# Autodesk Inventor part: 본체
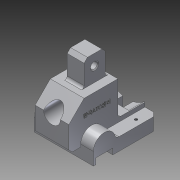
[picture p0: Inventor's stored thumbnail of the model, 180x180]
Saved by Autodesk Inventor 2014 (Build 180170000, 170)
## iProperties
Created: 2016-11
Part Number: 본체
Material: Aluminum 6061
Document SubType Name: Modeling
Designer: user
Density: 2.71 g/cm^3
Appearance: Aluminum - Flat
Author: user
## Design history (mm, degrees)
sketch "Sketch1"
  geometry: L1 (0, 0)-(0, 15); L2 (26, 15)-(76, 15); L3 (76, 15)-(76, 0); L4 (76, 0)-(0, 0); A1 r 13 centre (13, 15) between (26, 15) and (0, 15)
  constraints: 8 end point, 2 parallel, 2 point on circle, 1 centre point, 1 horizontal alignment, 1 perpendicular, 1 point on line, 1 vertical
  dimensions: "d1" = 15 distance of L1.start L1.end; "d2" = 76 distance of L3.end L1.start; "d3" = 26 diameter of A1
extrude "Extrusion1" new body sketch "Sketch1" distance "d4" = 70; taper "d5" = 0 deg
sketch "Sketch2"
  geometry: L1 (0, 0)-(-15, 0) reference; L2 (0, 76)-(0, 0) reference; L3 (-15, 26)-(-15, 76) reference; L4 (0, 3)-(-7, 3); L5 (-7, 3)-(-7, 23); L6 (-7, 23)-(0, 23)
  constraints: 6 end point, 3 perpendicular, 2 point on line
  dimensions: "d6" = 7 distance of L5.end L6.end; "d7" = 20 distance of L4.end L5.end; "d8" = 3 distance between parallel lines of L1 L4
extrude "Extrusion2" cut sketch "Sketch2" distance "d9" = 70; taper "d10" = 0 deg
workplane "Work Plane1"
sketch "Sketch3"
  geometry: L1 (23, 0)-(23, 7) reference; L2 (23, 7)-(3, 7) reference; L3 (3, 7)-(3, 0) reference; L4 (3, 0)-(0, 0) reference; L5 (0, 0)-(0, 15) reference; L6 (26, 15)-(76, 15) reference; L7 (76, 15)-(76, 0) reference; L8 (76, 0)-(23, 0) reference; L9 (76, 15)-(76, 20); L10 (76, 20)-(44, 20); L11 (44, 20)-(44, 15); A1 r 13 centre (13, 15) between (26, 15) and (0, 15) reference; 1 further point
  constraints: 6 end point, 3 perpendicular, 1 point on line
  dimensions: "d12" = 32 distance of L9.end L10.end; "d13" = 5 distance of L10.end L11.end
extrude "Extrusion3" join sketch "Sketch3" distance "d14" = 40; taper "d15" = 0 deg
sketch "Sketch4"
  geometry: L1 (23, 0)-(23, 7) reference; L2 (23, 7)-(3, 7) reference; L3 (3, 7)-(3, 0) reference; L4 (3, 0)-(0, 0) reference; L5 (0, 0)-(0, 15) reference; L6 (26, 15)-(76, 15) reference; L7 (76, 15)-(76, 0) reference; L8 (76, 0)-(23, 0) reference; L9 (76, 20)-(76, 15) reference; L10 (44, 15)-(76, 15) reference; L11 (44, 15)-(44, 20) reference; L12 (44, 20)-(76, 20) reference; L13 (44, 20)-(44, 60); L14 (44, 60)-(4, 60); L15 (4, 60)-(-14, 42); L16 (-14, 42)-(-14, 12); L17 (-14, 12)-(0, 12); L18 (44, 20)-(44, 15); L19 (44, 15)-(26, 15); L20 (0, 15)-(0, 12); A1 r 13 centre (13, 15) between (26, 15) and (0, 15) reference; A2 r 13 centre (13, 15) between (26, 15) and (0, 15); 1 further point
  constraints: 16 end point, 5 perpendicular, 2 parallel, 2 point on circle, 2 point on line, 2 tangent, 1 centre point, 1 coincident, 1 collinear
  dimensions: "d18" = 45 deg angle of L15 L14; "d21" = 48 distance between parallel lines of L17 L14; "d22" = 60 distance between parallel lines of L8 L14; "d23" = 30 distance of L15.end L16.end; "d24" = 40 distance of L13.end L14.end
extrude "Extrusion4" join sketch "Sketch4" distance "d25" = 40; taper "d26" = 0 deg
workplane "Work Plane2"
sketch "Sketch5"
  geometry: L1 (44, 60)-(4, 60) reference; L2 (39, 60)-(39, 90); L3 (39, 90)-(14, 90); L4 (14, 90)-(14, 60); L5 (39, 60)-(14, 60); L6 (76, 0)-(23, 0) reference; L7 (44, 60)-(44, 20) reference; 1 further point
  constraints: 8 end point, 3 perpendicular, 2 point on line, 1 collinear
  dimensions: "d28" = 90 distance between parallel lines of L6 L3; "d29" = 25 distance of L2.end L3.end; "d30" = 5 distance between parallel lines of L7 L2
extrude "Extrusion5" join sketch "Sketch5" stored distance "d31" = 20; taper "d32" = 0 deg
sketch "Sketch6"
  geometry: L1 (0, 15)-(-70, 15) reference; C1 r 29 at (-35, -27); 1 further point
  constraints: 1 centre point, 1 midpoint, 1 vertical alignment
  dimensions: "d33" = 58 diameter of C1; "d34" = 42 distance from line of L1 C1.centre
extrude "Extrusion6" cut sketch "Sketch6" distance "d35" = 18; taper "d36" = 0 deg
sketch "Sketch7"
  geometry: L1 (0, 15)-(-70, 15) reference; L2 (-53.894, -5)-(-55, -5) reference; L3 (-29, 15)-(-29, 1.373); L4 (-41, 15)-(-41, 1.373); L5 (-41, 15)-(-29, 15); A1 r 29 centre (-35, -27) between (-16.106, -5) and (-53.894, -5) reference; 2 further points
  constraints: 6 end point, 2 midpoint, 2 point on circle, 2 point on line, 2 vertical alignment, 1 parallel, 1 perpendicular
  dimensions: "d37" = 12 distance between parallel lines of L4 L3
extrude "Extrusion7" cut sketch "Sketch7" distance "d38" = 18; taper "d39" = 0 deg
sketch "Sketch8"
  geometry: L1 (0, 0)-(0, 50) reference; L2 (0, 50)-(-15, 50) reference; L3 (-55, 50)-(-70, 50) reference; 3 further points
  dimensions: "d40" = 18 distance from line of L2 point (-7.5, 32); "d41" = 18 distance from line of L3 point (-62.5, 32); "d42" = 55 distance of point (-7.5, 32) point (-62.5, 32); "d43" = 7.5 distance from line of L1 point (-7.5, 32)
hole "Hole1" sketch "Sketch8" at (-7.5, 32), (-62.5, 32) diameter "d44" = 3.242; stored, may be unused: countersink angle "d48" = 90 deg, drill point angle "d50" = 118 deg; dims "d45" = 15, "d46" = 4, "d47" = 2, "d49" = 8
sketch "Sketch9"
  geometry: L1 (-26, 60)-(-14, 60) reference; C1 r 14.5 at (-20, 18); 2 further points
  constraints: 1 centre point, 1 midpoint, 1 vertical alignment
  dimensions: "d51" = 29 diameter of C1; "d52" = 42 distance from line of L1 C1.centre
extrude "Extrusion8" cut sketch "Sketch9" distance "d53" = 7; taper "d54" = 0 deg
sketch "Sketch10"
  geometry: C1 r 14.5 at (0, 0) reference; C2 r 10 at (0, 0); 1 further point
  constraints: 1 centre point, 1 coincident
  dimensions: "d55" = 20 diameter of C2
extrude "Extrusion9" cut sketch "Sketch10" stored distance "d56" = 7; taper "d57" = 0 deg
sketch "Sketch11"
  geometry: L1 (-60, 39)-(-90, 39) reference; L2 (0, 76)-(0, 23) reference; C1 r 4 at (-77, 26.5); 1 further point
  constraints: 1 centre point
  dimensions: "d58" = 8 diameter of C1; "d59" = 12.5 distance from line of L1 C1.centre; "d60" = 77 distance from line of L2 C1.centre
extrude "Extrusion10" cut sketch "Sketch11" stored distance "d61" = 7; taper "d62" = 0 deg
chamfer "Chamfer1" distance "d63" = 4; stored, may be unused: second distance "d64" = 2, angle "d65" = 45 deg
chamfer "Chamfer2" distance "d66" = 1; stored, may be unused: second distance "d67" = 2, angle "d68" = 45 deg
chamfer "Chamfer3" distance "d69" = 5; stored, may be unused: second distance "d70" = 2, angle "d71" = 45 deg
fillet "Fillet1" dims "d72" = 5
fillet "Fillet2" dims "d73" = 3
workplane "Work Plane3"
sketch "Sketch12"
  geometry: L1 (-23, 44)-(-60, 44) reference; L2 (-60, 44)-(-60, 4) reference; 2 further points
  constraints: 1 other
  dimensions: "d75" = 25 distance from line of L1 point (-42, 19); "d76" = 18 distance from line of L2 point (-42, 19)
emboss "Emboss1" sketch "Sketch12" dims "d1" = 15, "d2" = 76, "d3" = 26, "d77" = 0.5, "d78" = 0
body "Solid1"
node "Projected Loop1"
node "Projected Loop2"
node "Projected Loop3"
other parameters: "d11" = -15, "d27" = -35, "d74" = 78.75
